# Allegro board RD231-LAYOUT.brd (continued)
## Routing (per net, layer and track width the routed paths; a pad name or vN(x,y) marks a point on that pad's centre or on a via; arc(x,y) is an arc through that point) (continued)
VP_12V: length 157.7
  TOP w0.35: 78.92,54.05 79.38,53.59 80.94,53.59 L2.1 ; 78.92,54.05 78.4,54.32 ; 78.92,54.05 78.65,54.57 ; 78.92,54.05 v1(78.49,54.48) ; 53.75,59.21 54.18,59.4 ; 53.75,59.21 v1(54.1,59.56) ; 53.75,59.21 53.72,59.18 52.32,59.18 51.05,57.91 51.05,54.23 50.42,53.59 47.34,53.59 L1.2 ; 53.75,59.21 53.94,59.64
  TOP w0.635: L3.1 29.84,84.26 29.84,102.87 27.64,105.08 26.42,105.08
  CONDUCTIVE3 w0.35: 69.85,72.21 v1(69.85,73.15) 69.85,74.09 ; 69.85,72.21 69.54,73.03 ; 69.85,72.21 69.71,73.03 ; 69.85,72.21 70.16,73.03 ; 69.85,72.21 69.89,73.03 ; 69.85,72.21 69.85,60.25 ; 69.85,74.09 69.85,79.12 69.47,79.5 58.04,79.5 56.01,77.47 56.01,57.58 ; 69.85,74.09 69.99,73.27 ; 69.85,74.09 69.81,73.27 ; 69.85,74.09 70.16,73.27 ; 69.85,74.09 69.54,73.27 ; 56.14,56.76 56.01,57.58 ; 56.01,57.58 55.97,56.76 ; 56.01,57.58 55.7,56.76 ; 56.01,57.58 v1(56.01,56.64) ; 56.01,57.58 56.32,56.76 ; 69.85,60.25 69.81,59.43 ; 69.85,60.25 v1(69.85,59.31) ; 69.85,60.25 69.54,59.43 ; 69.85,60.25 69.99,59.43 ; 69.85,60.25 70.16,59.43
  BOTTOM w0.35: 66.12,52.5 66.12,51.94 69.34,51.94 71.37,53.98 72.14,53.98 C18.1 R19.2 74.93,54.48 77.88,54.48 ; 69.85,58.7 70.02,59.26 ; 69.85,58.7 v1(69.85,59.31) ; 69.85,58.7 69.68,59.26 ; 69.85,58.7 R22.1 ; R23.2 R24.2 C27.1 55.4,56.64 ; 78.43,54.66 77.88,54.48 ; 77.88,54.48 v1(78.49,54.48) ; 77.88,54.48 78.43,54.31 ; 55.95,56.81 55.4,56.64 ; 55.4,56.64 55.95,56.47 ; 55.4,56.64 v1(56.01,56.64) ; 54.71,59.56 58.42,59.56 R18.1 C17.2 59.56,54.74 60.62,53.68 IC1.1 ; 54.71,59.56 54.16,59.39 ; 54.71,59.56 54.16,59.74 ; 54.71,59.56 v1(54.1,59.56)
VP_50_VIN: length 20.4
  TOP w0.3: 49.2,8.26 E1.4 49.59,13.72 55.82,13.72 E1.1
  BOTTOM w0.635: R1.1 R5.2 63.37,32 64.19,31.19 ; 64.19,31.19 v1(64.52,30.86) ; 64.19,31.19 64.49,30.84 ; 64.19,31.19 64.54,30.89
N00200018: length 51
  TOP w0.35: L1.1 47.34,52.96 50.8,52.96 51.69,53.85 51.69,57.66 52.45,58.42 53.49,58.42 ; 53.49,58.42 54.05,58.25 ; 53.49,58.42 54.05,58.59 ; 53.49,58.42 v1(54.1,58.42)
  CONDUCTIVE3 w0.635: 51.39,44.76 50.63,44.58 ; 50.63,44.58 v1(51.44,44.58) ; 50.63,44.58 51.39,44.39 ; 50.63,44.58 49.4,44.58 47.75,42.93 35.43,42.93 34.86,42.35 ; 34.86,42.35 v1(34.29,41.78) ; 34.86,42.35 34.45,41.68 ; 34.86,42.35 34.19,41.95
  BOTTOM w0.35: v1(54.1,58.42) 54.71,58.42 ; 54.71,58.42 54.16,58.25 ; 54.71,58.42 R21.2 ; 54.71,58.42 54.16,58.59 ; 57.01,46.98 56.64,46.61 ; 57.01,46.98 57.54,47.51 IC1.41 ; 57.01,46.98 56.77,46.54 ; 57.01,46.98 56.57,46.73
  BOTTOM w0.635: 51.76,44.91 v1(51.44,44.58) ; 51.76,44.91 51.41,44.61 ; 51.76,44.91 52.06,45.2 C19.2 55.23,45.2 56.64,46.61 ; 51.76,44.91 51.46,44.55
N00400009: length 20.6
  TOP w0.35: R76.1 52.07,143.26 46.99,143.26 L4.1
  TOP w0.635: 47.92,125.09 46.35,125.09 45.59,125.86 C69.2 ; 47.92,125.09 48.38,125.06 ; 47.92,125.09 48.38,125.13 ; 47.92,125.09 v1(48.39,125.09)
  BOTTOM w0.635: 48.38,125.13 47.92,125.09 ; 47.92,125.09 48.38,125.06 ; 47.92,125.09 45.47,125.09 43.94,126.62 43.94,127 ; 47.92,125.09 v1(48.39,125.09)
N00400011: length 20.5
  TOP w0.35: R77.1 104.27,143.13 99.06,143.13 L5.1
  TOP w0.635: C70.2 97.41,125.86 98.17,125.09 99.74,125.09 ; 99.74,125.09 100.2,125.13 ; 99.74,125.09 v1(100.2,125.09) ; 99.74,125.09 100.2,125.06
  BOTTOM w0.635: 99.74,125.09 100.2,125.06 ; 99.74,125.09 100.2,125.13 ; 99.74,125.09 97.16,125.09 95.76,126.49 95.76,127 ; 99.74,125.09 v1(100.2,125.09)
N00400014: length 20.3
  TOP w0.35: R78.1 26.16,143.26 20.95,143.26 L6.1
  TOP w0.635: C71.2 21.08,125.09 22.01,125.09 ; 22.48,125.13 22.01,125.09 ; 22.01,125.09 v1(22.48,125.09) ; 22.01,125.09 22.48,125.06
  BOTTOM w0.635: 22.48,125.13 22.01,125.09 ; 22.01,125.09 22.48,125.06 ; 22.01,125.09 19.94,125.09 18.03,127 18.03,127.13 ; 22.01,125.09 v1(22.48,125.09)
N00400017: length 20.6
  TOP w0.35: R79.1 78.61,142.75 78.11,143.26 73.03,143.26 L7.1
  TOP w0.635: 74.29,125.13 73.83,125.09 ; 73.83,125.09 72.26,125.09 71.5,125.86 C93.2 ; 73.83,125.09 74.29,125.06 ; 73.83,125.09 v1(74.3,125.09)
  BOTTOM w0.635: 73.83,125.09 v1(74.3,125.09) ; 73.83,125.09 74.29,125.13 ; 73.83,125.09 74.29,125.06 ; 73.83,125.09 71.75,125.09 69.85,127 69.85,127.13
N00400020: length 20.6
  TOP w0.35: L8.1 125.09,143.26 130.18,143.26 R80.1
  TOP w0.635: v1(126.11,125.09) 125.65,125.09 ; 125.65,125.09 126.11,125.13 ; 125.65,125.09 124.08,125.09 123.32,125.86 C94.2 ; 125.65,125.09 126.11,125.06
  BOTTOM w0.635: 125.65,125.09 v1(126.11,125.09) ; 125.65,125.09 126.11,125.06 ; 125.65,125.09 123.57,125.09 121.67,127 121.67,127.13 ; 125.65,125.09 126.11,125.13
N00400039: length 1.9
  BOTTOM w0.635: v1(29.72,130.05) 28.92,129.25 R92.2

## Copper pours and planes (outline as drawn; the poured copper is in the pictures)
LGND on TOP: 88.72,31.49 88.66,31.52 88.65,31.54 88.64,31.57 88.64,35.36 88.65,35.39 88.67,35.41 88.69,35.43 88.72,35.44 91.31,35.44 91.69,35.82 91.69,39.75 91.69,39.75 93.6,39.75 93.6,39.76 93.85,40.01 93.85,41.58 93.86,41.61 93.87,41.64 93.9,41.65 93.93,41.66 97.21,41.66 97.24,41.65 97.26,41.64 97.28,41.61 97.29,41.58 97.29,32.67 97.28,32.64 97.26,32.61 96.16,31.51 96.14,31.5 96.11,31.49
LGND on TOP: 15.57,126.36 15.51,126.38 15.5,126.41 15.49,126.44 15.49,130.86 15.5,130.89 15.51,130.92 15.54,130.94 15.57,130.94 18.47,130.94 18.5,130.93 18.52,130.92 18.54,130.89 18.55,130.86 18.55,128.05 18.54,128.02 18.52,127.99 17.72,127.19 17.55,127.02 17.53,127 17.52,126.62 17.51,126.59 17.3,126.38 17.27,126.37 17.24,126.36
LGND on TOP: outline of 96 points within 82.93,5.71 146.05,109.48 ; 1 cut-out
LGND on TOP: 67.38,126.36 67.33,126.38 67.31,126.41 67.31,126.44 67.31,130.86 67.31,130.89 67.33,130.92 67.36,130.94 67.39,130.94 70.28,130.94 70.31,130.93 70.34,130.92 70.36,130.89 70.36,130.86 70.36,128.05 70.36,128.02 70.34,127.99 69.54,127.19 69.35,127 69.34,126.62 69.32,126.59 69.11,126.38 69.09,126.37 69.06,126.36
LGND on TOP: 41.1,33.65 41.04,33.67 41.02,33.7 41.02,33.73 41.02,35.36 41.02,35.39 41.04,35.41 41.07,35.43 41.1,35.44 43.69,35.44 44.06,35.82 44.06,39.75 44.07,39.75 46.1,39.75 46.22,39.87 46.22,40.99 46.23,41.02 46.25,41.05 46.58,41.38 46.61,41.4 46.64,41.41 50.01,41.41 50.04,41.4 50.06,41.38 54.85,36.6 54.86,36.57 54.87,36.55 54.87,35.38 54.86,35.35 54.84,35.32 54.82,35.31 54.79,35.3 50.55,35.3 48.92,33.67 48.89,33.66 48.86,33.65
LGND on TOP: 5.28,121.66 5.23,121.69 5.21,121.71 5.2,121.74 5.2,158.04 5.21,158.07 5.23,158.1 5.25,158.11 5.28,158.12 14.07,158.12 14.1,158.11 14.12,158.1 14.21,158.01 14.22,157.99 14.23,157.96 14.23,146.05 14.99,145.29 19.15,145.29 19.19,145.29 19.21,145.27 19.23,145.24 19.23,145.21 19.23,136.73 20.17,135.79 20.19,135.76 20.2,135.73 20.2,131.3 20.19,131.27 20.17,131.24 20.15,131.22 20.12,131.22 12.55,131.22 12.53,131.22 12.37,131.25 12.22,131.25 12.07,131.21 11.94,131.13 11.82,131.03 11.74,130.9 11.69,130.76 11.67,130.6 11.67,127.54 11.66,127.51 11.64,127.48 11.59,127.42 11.55,127.34 11.52,127.26 11.52,127.18 11.52,125.81 11.52,125.72 11.55,125.64 11.59,125.57 11.64,125.51 11.7,125.46 11.77,125.42 11.85,125.39 11.94,125.38 13.66,125.38 13.69,125.38 13.71,125.36 13.73,125.33 13.74,125.31 13.74,121.95 13.73,121.92 13.71,121.9 13.5,121.68 13.48,121.67 13.45,121.66
LGND on TOP: 41.48,126.36 41.42,126.38 41.4,126.41 41.4,126.44 41.4,130.86 41.4,130.89 41.42,130.92 41.45,130.94 41.48,130.94 44.38,130.94 44.41,130.93 44.43,130.92 44.45,130.89 44.45,130.86 44.45,128.05 44.45,128.02 44.43,127.99 43.63,127.19 43.44,127 43.43,126.62 43.41,126.59 43.2,126.38 43.18,126.37 43.15,126.36
LGND on TOP: outline of 99 points within 5.2,5.71 45.72,94.62 ; 1 cut-out
LGND on TOP: 49.91,102.48 49.91,102.49 49.78,102.62 49.78,104.4 52.2,104.4 52.2,102.74 51.97,102.51 51.94,102.49 51.91,102.48
LGND on TOP: outline of 108 points within 106.68,120.52 123.96,158.25
LGND on TOP: 57.18,65.91 57.13,65.93 56.91,66.14 56.9,66.17 56.89,66.2 56.89,72.87 56.9,72.9 56.92,72.92 57.13,73.13 57.15,73.15 57.18,73.16 65.12,73.16 65.15,73.15 65.18,73.13 65.51,72.8 65.53,72.77 65.54,72.74 65.54,66.2 65.53,66.17 65.51,66.14 65.3,65.93 65.28,65.91 65.25,65.91
LGND on TOP: outline of 91 points within 28.95,120.65 45.98,158.25
LGND on TOP: 61.09,102.48 61.09,102.49 60.96,102.62 60.96,104.4 63.12,104.4 63.12,102.87 63.12,102.87 62.76,102.51 62.74,102.49 62.71,102.48
LGND on TOP: 93.29,126.36 93.24,126.38 93.22,126.41 93.21,126.44 93.21,130.86 93.22,130.89 93.24,130.92 93.26,130.94 93.29,130.94 96.19,130.94 96.22,130.93 96.25,130.92 96.26,130.89 96.27,130.86 96.27,128.05 96.26,128.02 96.25,127.99 95.45,127.19 95.25,127 95.25,126.62 95.23,126.59 95.02,126.38 94.99,126.37 94.97,126.36
LGND on TOP: 69.54,17.65 69.49,17.67 69.47,17.7 69.47,17.73 69.47,24.23 69.47,24.26 69.49,24.28 69.7,24.49 69.72,24.51 69.75,24.52 88.95,24.51 88.98,24.51 89.01,24.49 89.03,24.47 89.03,24.44 89.03,17.73 89.02,17.7 89.01,17.67 88.98,17.65 88.95,17.65
LGND on TOP: outline of 91 points within 54.86,120.52 71.89,158.12
LGND on TOP: 76.99,69.59 76.94,69.62 76.6,69.95 76.58,69.98 76.58,70.01 76.58,77.44 76.58,77.47 76.6,77.49 77.19,78.09 77.22,78.1 77.25,78.11 84.3,78.11 84.33,78.1 84.35,78.09 85.2,77.24 85.22,77.21 85.22,77.19 85.22,69.67 85.21,69.64 85.2,69.61 85.17,69.6 85.14,69.59
LGND on TOP: outline of 102 points within 80.77,120.55 97.92,158.12
LGND on TOP: 39.83,17.65 39.77,17.67 39.75,17.7 39.75,17.73 39.75,24.44 39.75,24.47 39.77,24.49 39.8,24.51 39.83,24.52 59.15,24.51 59.18,24.51 59.21,24.49 59.42,24.28 59.43,24.26 59.44,24.23 59.44,17.73 59.43,17.7 59.42,17.67 59.39,17.65 59.36,17.65
LGND on TOP: 52.78,170.18 52.75,170.18 52.72,170.2 52.71,170.23 52.7,170.25 52.7,182.93 52.71,182.96 52.72,182.99 52.75,183.01 52.78,183.01 62.79,183.01 62.82,183 62.85,182.99 62.86,182.96 62.87,182.93 62.87,170.25 62.86,170.22 62.85,170.2 62.82,170.18 62.79,170.18
LGND on TOP: 119.2,126.36 119.14,126.38 119.13,126.41 119.12,126.44 119.12,130.86 119.13,130.89 119.15,130.92 119.17,130.94 119.2,130.94 122.1,130.94 122.13,130.93 122.16,130.92 122.17,130.89 122.18,130.86 122.18,128.05 122.17,128.02 122.15,127.99 121.36,127.19 121.16,127 121.15,126.62 121.14,126.59 120.93,126.38 120.9,126.37 120.87,126.36
LGND on TOP: 132.66,120.52 132.61,120.54 132.59,120.57 132.58,120.6 132.58,128.01 132.59,128.02 134.36,128.02 134.53,128.18 134.53,129.54 134.52,129.54 134.52,130.14 133.86,130.81 132.58,130.81 132.58,134.11 132.59,134.11 134.36,134.11 134.53,134.28 134.53,152.43 134.75,152.5 134.75,153.32 134.53,153.39 134.53,153.95 134.75,154.02 134.75,154.84 134.53,154.91 134.53,192.97 134.53,193 134.55,193.02 134.57,193.04 134.6,193.04 141.53,193.04 141.56,193.04 141.59,193.02 141.6,192.99 141.61,192.97 141.61,191.14 144.15,188.6 145.98,188.6 146.01,188.59 146.03,188.58 146.05,188.55 146.05,188.52 146.05,120.6 146.05,120.57 146.03,120.54 146,120.52 145.98,120.52 ; 1 cut-out
LGND on BOTTOM: outline of 288 points within 37.97,86.32 63.16,108.21 ; 7 cut-outs
LGND on BOTTOM: 15.75,129.26 15.57,129.4 15.21,129.4 15.16,129.41 15.1,129.42 14.66,129.42 14.64,129.43 14.03,130.05 13.08,131.19 17.14,131.19
LGND on BOTTOM: 93.47,129.29 93.34,129.41 92.88,129.41 92.82,129.42 92.46,129.42 92.44,129.43 91.82,130.05 90.81,131.19 94.87,131.19 95,131.06 95,125.99
LGND on BOTTOM: 5.28,78.36 5.23,78.38 5.21,78.4 5.2,78.43 5.2,94.54 5.21,94.57 5.23,94.6 5.25,94.61 5.28,94.62 6.98,94.62 9.52,97.16 9.52,101.29 9.53,101.32 9.54,101.34 9.57,101.36 9.6,101.37 11.68,101.37 11.82,101.38 11.95,101.4 12.07,101.45 12.19,101.5 12.29,101.58 12.39,101.66 12.48,101.76 12.55,101.88 13.16,102.97 13.17,102.98 16.14,105.95 16.17,105.97 16.2,105.97 27.61,105.97 27.64,105.97 27.67,105.95 27.68,105.92 27.69,105.9 27.69,78.43 27.68,78.4 27.67,78.38 27.64,78.36 27.61,78.36
LGND on BOTTOM: 119.38,129.26 119.2,129.4 118.84,129.4 118.8,129.41 118.73,129.42 118.29,129.42 118.28,129.43 117.66,130.05 116.71,131.19 120.78,131.19
LGND on BOTTOM: outline of 116 points within 5.2,5.71 146.05,193.04 ; 33 cut-outs
LGND on BOTTOM: 66.11,43.05 66.05,43.11 66.05,43.13 66.05,44.1 66.04,44.12 66.04,44.71 67.49,44.71 67.52,44.7 67.55,44.68 67.56,44.66 67.57,44.63 67.57,43.13 67.56,43.1 67.54,43.07 67.52,43.05 67.49,43.05
LGND on BOTTOM: 41.66,129.29 41.53,129.41 41.07,129.41 41,129.42 40.64,129.42 40.62,129.43 40.01,130.05 38.99,131.19 43.05,131.19
LGND on BOTTOM: 67.56,129.26 67.38,129.4 67.03,129.4 66.98,129.41 66.91,129.42 66.48,129.42 66.46,129.43 65.84,130.05 64.9,131.19 68.96,131.19
LGND on BOTTOM: 28.27,78.36 28.21,78.38 28.2,78.4 28.19,78.43 28.19,105.9 28.2,105.93 28.21,105.95 28.24,105.97 28.27,105.98 33.63,105.98 33.65,105.97 33.78,105.95 33.91,105.94 34.04,105.95 34.17,105.97 34.19,105.98 37.65,105.98 37.68,105.97 37.7,105.95 41.76,101.89 41.78,101.87 41.79,101.84 41.79,99.07 41.78,99.04 41.76,99.02 41.48,98.73 41.4,98.64 41.34,98.53 41.31,98.42 41.3,98.3 41.3,97.03 41.31,96.91 41.34,96.79 41.4,96.69 41.48,96.59 42.29,95.78 42.31,95.75 42.31,95.73 42.31,87.63 42.32,87.51 42.36,87.4 42.42,87.29 42.49,87.2 43.92,85.76 43.94,85.74 43.95,85.71 43.95,78.77 43.94,78.74 43.92,78.72 43.59,78.38 43.56,78.36 43.53,78.36 ; 2 cut-outs
LGND on CONDUCTIVE2: outline of 1020 points within 5.2,108.07 146.05,193.04 ; 191 cut-outs
LGND on CONDUCTIVE2: 28.27,78.48 28.21,78.51 28.2,78.53 28.19,78.56 28.19,112.7 28.2,112.73 28.21,112.76 28.24,112.77 28.27,112.78 33.22,112.78 33.25,112.77 33.27,112.76 33.29,112.73 33.3,112.7 33.3,108.43 33.29,108.41 32.92,107.05 32.92,106.9 32.93,106.75 32.97,106.6 33.03,106.46 33.11,106.34 33.22,106.22 33.34,106.12 33.47,106.04 33.61,105.98 33.76,105.95 33.91,105.94 34.06,105.95 34.21,105.98 34.35,106.04 34.48,106.12 34.6,106.22 34.7,106.34 34.78,106.46 34.85,106.6 34.89,106.75 34.9,106.9 34.9,107.05 34.87,107.21 34.53,108.41 34.52,108.43 34.52,112.7 34.53,112.73 34.55,112.76 34.57,112.77 34.6,112.78 42.09,112.78 42.12,112.77 42.15,112.76 42.16,112.73 42.17,112.7 42.17,97.82 42.16,97.79 42.13,97.67 42.12,97.54 42.13,97.41 42.16,97.28 42.17,97.25 42.17,78.56 42.16,78.53 42.14,78.5 42.12,78.49 42.09,78.48 ; 2 cut-outs
LGND on CONDUCTIVE2: 55.07,33.27 55.04,33.28 55.01,33.29 54.99,33.32 54.99,33.35 54.99,36.45 51.11,40.32 50.18,41.25 50.17,41.28 50.16,41.31 50.16,58.01 50.17,58.04 50.18,58.06 53.57,61.45 53.6,61.47 53.62,61.47 74.77,61.47 74.8,61.47 74.83,61.45 78.09,58.19 78.1,58.16 78.11,58.13 78.11,54.83 78.09,54.79 78.05,54.72 78.02,54.64 78,54.56 77.99,54.48 78,54.4 78.02,54.33 78.05,54.25 78.09,54.18 78.11,54.13 78.11,53.69 78.09,53.64 78.05,53.57 78.02,53.5 78,53.42 77.99,53.34 78,53.26 78.02,53.18 78.05,53.11 78.09,53.04 78.11,52.99 78.11,37.75 78.1,37.72 78.09,37.69 73.68,33.29 73.66,33.28 73.63,33.27 ; 20 cut-outs
LGND on CONDUCTIVE2: 5.28,78.48 5.25,78.49 5.23,78.51 5.21,78.53 5.2,78.56 5.2,95.69 5.21,95.72 5.22,95.75 5.25,95.76 5.28,95.77 5.6,95.8 5.91,95.87 6.21,95.96 6.5,96.08 6.77,96.23 7.02,96.4 7.26,96.59 7.48,96.8 7.68,97.03 7.85,97.28 8.01,97.55 8.14,97.82 8.24,98.12 8.31,98.42 8.36,98.74 8.38,99.06 8.36,99.38 8.31,99.7 8.24,100 8.14,100.3 8.01,100.57 7.85,100.84 7.68,101.09 7.48,101.32 7.26,101.53 7.02,101.72 6.77,101.89 6.5,102.04 6.21,102.16 5.91,102.25 5.6,102.32 5.28,102.35 5.25,102.36 5.22,102.38 5.21,102.4 5.2,102.43 5.2,115.75 5.21,115.78 5.23,115.81 5.25,115.82 5.28,115.83 14.96,115.83 14.99,115.82 15.01,115.8 15.75,115.07 19.74,115.07 19.77,115.06 19.79,115.04 19.81,115.02 19.82,114.99 19.82,113.03 20.07,112.78 27.36,112.78 27.39,112.77 27.41,112.76 27.43,112.73 27.44,112.7 27.44,78.56 27.43,78.53 27.41,78.5 27.39,78.49 27.36,78.48 ; 1 cut-out
LGND on CONDUCTIVE2: outline of 152 points within 5.2,5.2 145.93,112.27 ; 9 cut-outs
LGND on CONDUCTIVE2: outline of 470 points within 42.51,78.48 83.19,112.79 ; 23 cut-outs
LGND on CONDUCTIVE3: outline of 172 points within 102.85,111.6 131.35,158.25 ; 8 cut-outs
LGND on CONDUCTIVE3: outline of 262 points within 27.94,79.75 79.89,112.27 ; 4 cut-outs
LGND on CONDUCTIVE3: outline of 290 points within 29.08,109.98 53.63,158.19 ; 7 cut-outs
LGND on CONDUCTIVE3: outline of 260 points within 54.86,109.98 79.64,158.12 ; 6 cut-outs
LGND on CONDUCTIVE3: outline of 270 points within 5.08,5.08 145.29,117.22 ; 5 cut-outs
LGND on CONDUCTIVE3: outline of 233 points within 78.7,113.12 105.45,158.25 ; 6 cut-outs
LGND on CONDUCTIVE3: outline of 224 points within 43.65,84.9 79.89,106.46 ; 14 cut-outs
LGND on CONDUCTIVE3: outline of 153 points within 127.12,109.94 144.06,189.16
LGND on CONDUCTIVE3: 5.28,79.75 5.25,79.76 5.23,79.78 5.21,79.8 5.2,79.83 5.2,95.69 5.21,95.72 5.22,95.75 5.25,95.76 5.28,95.77 5.6,95.8 5.91,95.87 6.21,95.96 6.5,96.08 6.77,96.23 7.02,96.4 7.26,96.59 7.48,96.8 7.68,97.03 7.85,97.28 8.01,97.55 8.14,97.82 8.24,98.12 8.31,98.42 8.36,98.74 8.38,99.06 8.36,99.38 8.31,99.7 8.24,100 8.14,100.3 8.01,100.57 7.85,100.84 7.68,101.09 7.48,101.32 7.26,101.53 7.02,101.72 6.77,101.89 6.5,102.04 6.21,102.16 5.91,102.25 5.6,102.32 5.28,102.35 5.25,102.36 5.22,102.38 5.21,102.4 5.2,102.43 5.2,112.19 5.21,112.22 5.23,112.25 5.25,112.27 5.28,112.27 27.1,112.27 27.13,112.27 27.16,112.25 27.18,112.22 27.18,112.19 27.18,79.83 27.18,79.8 27.16,79.77 27.13,79.76 27.1,79.75 ; 1 cut-out
LGND on CONDUCTIVE3: outline of 250 points within 51.56,40.26 69.38,78.81 ; 1 cut-out
LGND on CONDUCTIVE3: outline of 116 points within 5.2,112.99 29.98,158.25 ; 6 cut-outs
LGND on CONDUCTIVE4: outline of 100 points within 5.2,117.47 146.05,192.92 ; 216 cut-outs
LGND on CONDUCTIVE4: outline of 379 points within 5.2,5.2 146.05,117.1 ; 54 cut-outs
LGND on CONDUCTIVE4: 55.07,33.27 55.04,33.28 55.01,33.29 54.99,33.32 54.99,33.35 54.99,36.45 51.11,40.32 50.18,41.25 50.17,41.28 50.16,41.31 50.16,58.01 50.17,58.04 50.18,58.06 53.57,61.45 53.6,61.47 53.62,61.47 74.77,61.47 74.8,61.47 74.83,61.45 78.09,58.19 78.1,58.16 78.11,58.13 78.11,54.83 78.09,54.79 78.05,54.72 78.02,54.64 78,54.56 77.99,54.48 78,54.4 78.02,54.33 78.05,54.25 78.09,54.18 78.11,54.13 78.11,53.69 78.09,53.64 78.05,53.57 78.02,53.5 78,53.42 77.99,53.34 78,53.26 78.02,53.18 78.05,53.11 78.09,53.04 78.11,52.99 78.11,37.75 78.1,37.72 78.09,37.69 73.68,33.29 73.66,33.28 73.63,33.27 ; 20 cut-outs
LGND on CONDUCTIVE5: 28.48,83.31 28.42,83.33 28.21,83.54 28.2,83.57 28.19,83.6 28.19,107.88 28.2,107.91 28.21,107.93 28.24,107.95 28.27,107.95 41.79,107.95 41.82,107.95 41.85,107.93 41.86,107.9 41.87,107.88 41.87,83.55 41.86,83.52 41.85,83.5 41.68,83.33 41.65,83.31 41.63,83.31 ; 4 cut-outs
LGND on CONDUCTIVE5: 55.07,33.27 55.04,33.28 55.01,33.29 54.99,33.32 54.99,33.35 54.99,36.45 51.11,40.32 50.18,41.25 50.17,41.28 50.16,41.31 50.16,58.01 50.17,58.04 50.18,58.06 53.57,61.45 53.6,61.47 53.62,61.47 74.77,61.47 74.8,61.47 74.83,61.45 78.09,58.19 78.1,58.16 78.11,58.13 78.11,54.83 78.09,54.79 78.05,54.72 78.02,54.64 78,54.56 77.99,54.48 78,54.4 78.02,54.33 78.05,54.25 78.09,54.18 78.11,54.13 78.11,53.69 78.09,53.64 78.05,53.57 78.02,53.5 78,53.42 77.99,53.34 78,53.26 78.02,53.18 78.05,53.11 78.09,53.04 78.11,52.99 78.11,37.75 78.1,37.72 78.09,37.69 73.68,33.29 73.66,33.28 73.63,33.27 ; 20 cut-outs
LGND on CONDUCTIVE5: outline of 281 points within 5.2,78.48 87,107.95 ; 34 cut-outs
LGND on CONDUCTIVE5: outline of 476 points within 5.2,5.2 146.05,192.97 ; 65 cut-outs
Net_1 on BOTTOM: 11.5,12 12.5,12
Net_2 on BOTTOM: 138.63,12 139.63,12
Net_3 on BOTTOM: 11.5,186.12 12.5,186.12
Net_4 on BOTTOM: 138.63,186.12 139.63,186.12
SIGN6423 on TOP: 44.07,40.26 44.06,40.26 44.06,41.02 44.58,41.53 45.52,41.53 45.55,41.53 45.57,41.51 45.59,41.48 45.6,41.45 45.6,40.51 45.59,40.51 45.34,40.26
SIGN6441 on TOP: 29.88,39.62 29.85,39.63 29.82,39.64 29.1,40.36 29.08,40.39 29.08,40.42 29.08,41.27 29.08,41.27 29.21,41.4 31.75,41.4 32.13,41.02 32.13,39.62
SIGN6613 on TOP: 106.68,134.62 106.65,134.65 106.65,135.58 106.66,135.61 106.68,135.64 107.14,136.1 107.17,136.12 107.2,136.13 107.64,136.13 107.67,136.12 107.7,136.1 107.91,135.89 107.91,134.85 107.71,134.62
SIGN6624 on TOP: 28.93,134.62 28.93,135.58 28.95,135.64 29.42,136.1 29.44,136.12 29.47,136.13 29.92,136.13 29.95,136.12 29.97,136.1 30.19,135.89 30.19,134.71 30.1,134.62
SIGN6683 on TOP: 132.59,134.62 132.56,134.65 132.56,135.58 132.57,135.61 132.59,135.64 133.05,136.1 133.08,136.12 133.11,136.13 133.55,136.13 133.58,136.12 133.61,136.1 133.82,135.89 133.82,134.66 133.78,134.62
SIGN6946 on BOTTOM: 58.17,43.45 58.16,43.49 58.16,45.39 58.17,45.42 58.19,45.45 58.21,45.46 58.24,45.47 59.82,45.47 59.82,44.95 58.3,43.43 58.26,43.41
SIGN7059 on TOP: 87.33,36.43 87.33,36.45 84.94,36.45 84.43,36.96 84.43,37.91 84.42,37.94 84.34,37.99 84.32,38.04 84.32,39.11 83.95,39.49 80.39,39.49 80.26,39.62 80.26,42.54 78.25,44.55 78.23,44.58 78.23,44.61 78.23,50.09 78.23,50.12 78.25,50.15 78.28,50.16 78.31,50.17 83.66,50.17 83.69,50.16 83.72,50.15 90.68,43.19 90.93,42.93 90.93,40.98 90.94,40.97 90.94,36.51 90.92,36.47 90.91,36.45 90.89,36.44 90.86,36.43
SIGN7073 on TOP: 77.37,39.62 77.34,39.63 77.32,39.64 76.73,40.23 76.71,40.26 76.7,40.29 76.7,41.27 76.83,41.4 79.63,41.4 79.76,41.27 79.76,39.62
SIGN7074 on TOP: 91.82,40.26 91.69,40.39 91.69,41.24 91.7,41.27 91.71,41.3 92.18,41.76 92.2,41.78 92.23,41.79 92.68,41.79 92.71,41.78 92.73,41.76 92.97,41.53 92.96,41.52 92.96,40.45 92.77,40.26
SIGN7122 on TOP: 54.94,128.52 54.84,128.63 54.84,129.49 54.84,129.52 54.86,129.54 55.33,130.01 55.35,130.02 55.38,130.03 55.83,130.03 55.86,130.02 55.88,130.01 56.13,129.76 56.13,128.52
SIGN7125 on TOP: 54.84,134.65 54.84,135.58 54.86,135.64 55.33,136.1 55.35,136.12 55.38,136.13 55.83,136.13 55.86,136.12 55.88,136.1 56.1,135.89 56.1,134.65
SIGN7136 on TOP: 106.76,128.52 106.65,128.63 106.65,129.49 106.66,129.52 106.68,129.54 107.14,130.01 107.17,130.02 107.2,130.03 107.64,130.03 107.67,130.02 107.7,130.01 107.91,129.79 107.91,128.66 107.8,128.52
SIGN7151 on TOP: 80.77,128.52 80.75,128.55 80.75,129.49 80.75,129.52 80.77,129.54 81.23,130.01 81.26,130.02 81.29,130.03 81.74,130.03 81.77,130.02 81.79,130.01 82,129.79 82,128.63 81.92,128.52
SIGN7152 on TOP: 80.77,134.62 80.75,134.65 80.75,135.58 80.75,135.61 80.77,135.64 81.23,136.1 81.26,136.12 81.29,136.13 81.74,136.13 81.77,136.12 81.79,136.1 82,135.89 82,134.66 81.96,134.62
SIGN7156 on TOP: 132.59,128.52 132.56,128.55 132.56,129.49 132.57,129.52 132.59,129.54 133.05,130.01 133.08,130.02 133.11,130.03 133.55,130.03 133.58,130.02 133.61,130.01 133.82,129.79 133.82,128.6 133.75,128.52
VP_1R2_VOUT on TOP: outline of 319 points within 5.21,145.29 134.11,193.04 ; 8 cut-outs
VP_1R2_VOUT on BOTTOM: 80.72,170.05 80.69,170.06 80.67,170.07 80.65,170.1 80.64,170.13 80.64,182.93 80.65,182.96 80.67,182.99 80.69,183 80.72,183.01 89.08,183.01 89.11,183 89.13,182.99 89.15,182.96 89.15,182.93 89.15,170.25 89.15,170.23 89.13,170.2 89.11,170.19 89.08,170.18 83.31,170.18 83.21,170.07 83.18,170.06 83.15,170.05
VP_1R2_VOUT on CONDUCTIVE3: outline of 258 points within 5.21,146.48 134.11,189.1 ; 6 cut-outs
VP_1R2_VOUT on CONDUCTIVE5: outline of 253 points within 5.21,146.05 134.11,192.91 ; 9 cut-outs
VP_12V on TOP: outline of 209 points within 5.2,56.38 146.05,121.42 ; 5 cut-outs
VP_50_VIN on TOP: outline of 90 points within 31.35,5.71 92.96,38.87
N00200018 on TOP: 39.71,36.43 39.71,36.45 37.08,36.45 36.8,36.73 36.8,38.04 36.79,38.07 36.75,38.09 36.71,38.12 36.7,38.16 36.7,39.24 36.32,39.62 32.77,39.62 32.64,39.75 32.64,42.81 32.79,42.95 40.11,50.27 40.13,50.29 40.16,50.3 49.96,50.3 49.99,50.29 50.02,50.27 50.04,50.25 50.04,50.22 50.04,46.3 50.04,46.27 50.02,46.25 49.99,46.23 49.96,46.22 47.25,46.22 45.69,44.67 44.39,43.37 43.31,42.29 43.31,40.98 43.31,40.97 43.31,36.51 43.3,36.47 43.28,36.45 43.26,36.44 43.23,36.43
N00400009 on TOP: outline of 102 points within 45.72,122.17 54.1,141.23
N00400011 on TOP: 102.31,122.17 102.28,122.18 102.25,122.19 102.24,122.22 102.23,122.25 102.23,124.33 101.85,124.71 99.31,124.71 99.22,124.82 99.19,124.82 99.16,124.84 98.99,125.01 98.98,125.03 98.97,125.06 98.97,125.86 98.97,125.86 98.97,127.51 98.98,127.55 99.02,127.63 99.05,127.71 99.07,127.8 99.08,127.89 99.07,127.98 99.05,128.06 99.02,128.15 98.98,128.23 98.97,128.27 98.97,128.78 98.98,128.82 99.04,128.94 99.07,129.07 99.07,129.21 99.05,129.34 99,129.46 98.93,129.58 98.83,129.67 98.72,129.74 98.69,129.76 98.44,130.01 98.43,130.03 98.42,130.06 98.42,136.27 97.81,136.88 97.79,136.91 97.79,136.94 97.79,141.15 97.79,141.18 97.81,141.21 97.83,141.22 97.86,141.23 105.66,141.23 105.92,140.97 105.92,135.34 105.92,135.33 105.92,130.87 105.92,130.85 105.92,129.25 105.92,129.23 105.92,124.77 105.92,124.75 105.92,122.3 105.79,122.17
N00400014 on TOP: 24.52,122.17 24.51,122.17 24.51,124.39 24.26,124.59 21.82,124.59 21.54,124.82 21.51,124.84 21.34,125.01 21.33,125.03 21.32,125.06 21.32,126.49 21.32,126.5 21.32,127.68 21.32,127.7 21.35,127.79 21.35,127.89 21.35,127.99 21.32,128.08 21.32,128.1 21.32,128.95 21.32,128.97 21.35,129.08 21.35,129.2 21.34,129.31 21.3,129.42 21.25,129.52 21.18,129.6 21.09,129.68 20.99,129.74 20.97,129.76 20.67,130.06 20.65,130.09 20.64,130.12 20.64,135.89 19.7,136.83 19.69,136.86 19.68,136.88 19.68,141.15 19.69,141.18 19.7,141.21 19.73,141.22 19.76,141.23 28.07,141.23 28.1,141.22 28.12,141.2 28.14,141.18 28.15,141.15 28.15,135.4 28.16,135.39 28.18,135.37 28.19,135.35 28.2,135.33 28.2,130.87 28.19,130.83 28.17,130.81 28.15,130.8 28.15,129.3 28.16,129.29 28.18,129.28 28.19,129.26 28.2,129.23 28.2,124.77 28.19,124.73 28.17,124.71 28.15,124.7 28.15,122.25 28.14,122.22 28.12,122.19 28.1,122.18 28.07,122.17
N00400017 on TOP: 76.4,122.17 76.35,122.19 76.33,122.22 76.32,122.25 76.32,124.33 75.94,124.71 73.48,124.71 73.28,124.82 73.25,124.84 73.08,125.01 73.07,125.03 73.06,125.06 73.06,125.86 73.06,125.86 73.06,127.51 73.07,127.55 73.11,127.63 73.14,127.71 73.16,127.8 73.17,127.89 73.16,127.98 73.14,128.06 73.11,128.15 73.07,128.23 73.06,128.27 73.06,128.78 73.07,128.82 73.13,128.94 73.16,129.07 73.17,129.21 73.14,129.34 73.09,129.46 73.02,129.58 72.92,129.67 72.81,129.74 72.79,129.76 72.41,130.14 72.39,130.16 72.39,130.19 72.39,136.27 71.77,136.88 71.76,136.91 71.75,136.94 71.75,141.15 71.76,141.18 71.77,141.21 71.8,141.22 71.83,141.23 79.88,141.23 80.01,141.1 80.01,135.34 80.01,135.33 80.01,130.87 80.01,130.85 80.01,129.25 80.01,129.23 80.01,124.77 80.01,124.75 80.01,122.3 79.88,122.17
N00400020 on TOP: 128.22,122.17 128.19,122.18 128.16,122.19 128.14,122.22 128.14,122.25 128.14,124.33 127.66,124.81 125.13,124.82 125.1,124.82 125.07,124.84 124.9,125.01 124.88,125.03 124.88,125.06 124.88,125.86 124.88,125.86 124.88,127.51 124.89,127.55 124.93,127.63 124.96,127.71 124.98,127.8 124.98,127.89 124.98,127.98 124.96,128.06 124.93,128.15 124.89,128.23 124.88,128.27 124.88,128.78 124.89,128.82 124.95,128.94 124.98,129.07 124.98,129.21 124.96,129.34 124.91,129.46 124.83,129.58 124.74,129.67 124.62,129.74 124.6,129.76 124.48,129.88 124.46,129.91 124.46,129.94 124.46,136.29 123.86,136.88 123.85,136.91 123.84,136.94 123.84,141.15 123.85,141.18 123.86,141.21 123.89,141.22 123.92,141.23 131.69,141.23 131.83,141.1 131.83,135.34 131.83,135.33 131.83,130.87 131.83,130.85 131.83,129.25 131.83,129.23 131.83,124.77 131.83,124.75 131.83,122.3 131.69,122.17
N00400039 on TOP: 28.93,128.52 28.93,129.61 28.94,129.64 28.95,129.67 29.42,130.13 29.44,130.15 29.47,130.16 29.92,130.16 29.95,130.15 29.97,130.13 30.19,129.92 30.19,128.61 30.1,128.52

Small or netless copper shapes (teardrops, artwork), in the pictures only: 15 on CONDUCTIVE2, 15 on CONDUCTIVE3, 15 on CONDUCTIVE4, 16 on BOTTOM
